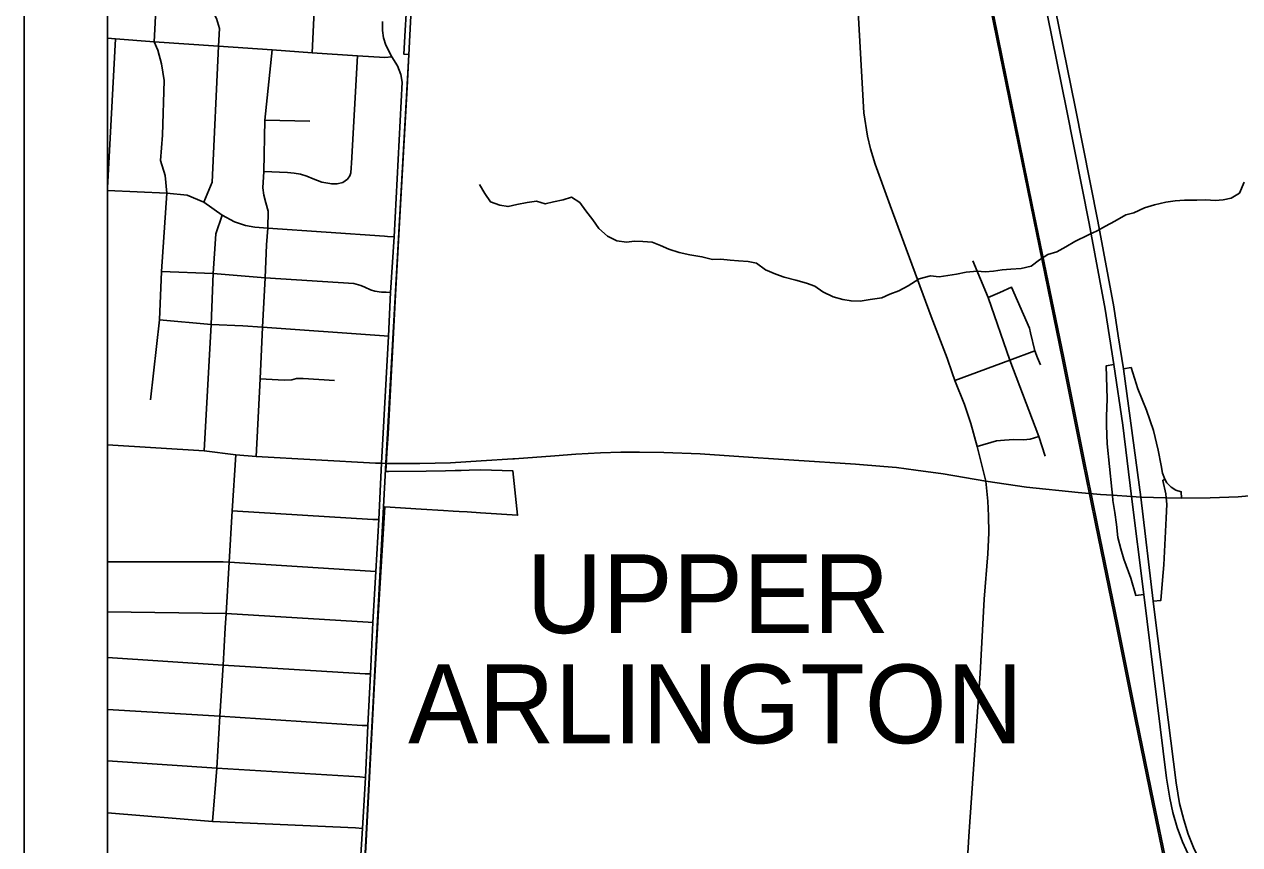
# Model space of a CAD drawing. Extents: x 0 to 34, y 0 to 22.
# Drawn here: x 3.318 to 4.779, y 13.965 to 14.951 of the extents above; entities that cross this region are included whole.
import ezdxf

# ---------------------------------------------------------------- set-up
doc = ezdxf.new("R2010")
doc.units = 0
for name, color, linetype in [('GM_X_City_Street', 7, 'Continuous'), ('GM_X_Corporation', 7, 'Continuous'), ('GM_X_Corporation_Text', 7, 'Continuous'), ('GM_X_County_Road', 7, 'Continuous'), ('GM_X_Interchange_Ramps', 7, 'Continuous'), ('GM_X_Minor_River', 7, 'Continuous'), ('GM_X_Rail_Line', 7, 'Continuous'), ('GM_X_State_Route', 7, 'Continuous'), ('GM_X_Township_Road', 7, 'Continuous'), ('SH_Data', 7, 'Continuous')]:
    doc.layers.add(name, color=color, linetype=linetype)

msp = doc.modelspace()

# ---------------------------------------------------------------- linework, layer by layer
at = {"layer": 'GM_X_City_Street'}
for p, q in [((3.6641, 14.9171), (3.6818, 15.2616)), ((3.4182, 14.7547), (3.428, 14.934)), ((3.6073, 14.8361), (3.6614, 14.8348))]:
    msp.add_line(p, q, dxfattribs=at)
for points in [[(3.4697, 14.5), (3.4807, 14.596), (3.4832, 14.6543), (3.4895, 14.7484), (3.4876, 14.7697), (3.482, 14.7879), (3.4845, 14.818), (3.4864, 14.8838), (3.4832, 14.9039), (3.4788, 14.9202), (3.4744, 14.9302), (3.4916, 15.2614), (3.4922, 15.2751), (3.4936, 15.2887), (3.4949, 15.3045), (3.5, 15.319), (3.5042, 15.3333), (3.5076, 15.3435), (3.5087, 15.3606), (3.5204, 15.5468), (3.5251, 15.614)], [(3.534, 14.7377), (3.544, 14.7615), (3.5516, 14.9252), (3.5528, 14.9465), (3.5491, 14.9584), (3.5422, 14.9722), (3.5365, 14.9891), (3.5503, 15.2711)], [(3.7228, 13.9529), (3.7248, 13.9848), (3.7282, 14.0461), (3.731, 14.1086), (3.7343, 14.1704), (3.737, 14.2323), (3.7409, 14.2935), (3.7442, 14.3562), (3.7475, 14.4237), (3.7562, 14.5767), (3.7585, 14.6291), (3.7628, 14.6959), (3.7723, 14.8819), (3.7707, 14.891), (3.767, 14.9016), (3.76, 14.9125), (3.7529, 14.9262), (3.7499, 14.9353), (3.7487, 14.944), (3.7487, 14.9549)], [(3.4182, 14.9347), (3.428, 14.934), (3.4744, 14.9302), (3.5516, 14.9252), (3.6161, 14.9208), (3.6641, 14.9171), (3.7187, 14.9134), (3.7517, 14.9117), (3.76, 14.9125)], [(3.5968, 14.4318), (3.6017, 14.5252), (3.6046, 14.5874), (3.6076, 14.6467), (3.6095, 14.6863), (3.6102, 14.6964), (3.6109, 14.7065), (3.6112, 14.7266), (3.6087, 14.7368), (3.6061, 14.7462), (3.6048, 14.7549), (3.6063, 14.7746), (3.6073, 14.8361), (3.6161, 14.9208)], [(3.6063, 14.7746), (3.6347, 14.7731), (3.6424, 14.7725), (3.6501, 14.7712), (3.658, 14.7689), (3.6656, 14.7656), (3.6758, 14.7616), (3.6878, 14.7595), (3.6942, 14.7597), (3.7013, 14.7611), (3.7067, 14.7651), (3.7095, 14.7692), (3.7109, 14.773), (3.7111, 14.7787), (3.7115, 14.7845), (3.7187, 14.9134)], [(3.4182, 14.7515), (3.4895, 14.7484), (3.5139, 14.7459), (3.534, 14.7377), (3.556, 14.722), (3.571, 14.7139), (3.5841, 14.7095), (3.5952, 14.7077), (3.6109, 14.7065), (3.7511, 14.6968), (3.755, 14.6965), (3.7628, 14.6959)], [(3.5344, 14.4385), (3.5428, 14.5904), (3.5453, 14.6518), (3.5484, 14.6995), (3.556, 14.722)], [(4.5455, 14.4322), (4.5377, 14.456), (4.5028, 14.5477), (4.477, 14.6228), (4.4585, 14.6672)], [(3.4832, 14.6543), (3.5453, 14.6518), (3.6076, 14.6467), (3.7143, 14.6398), (3.7226, 14.6375), (3.7274, 14.6355), (3.7342, 14.6322), (3.7394, 14.6306), (3.7475, 14.6294), (3.753, 14.6293), (3.7585, 14.6291)], [(3.4807, 14.596), (3.5428, 14.5904), (3.5808, 14.5888), (3.6046, 14.5874), (3.745, 14.5773), (3.7506, 14.577), (3.7562, 14.5767)], [(4.4368, 14.5232), (4.5028, 14.5477), (4.533, 14.559)], [(3.6017, 14.5252), (3.6306, 14.5237), (3.6397, 14.524), (3.6455, 14.5255), (3.6534, 14.5257), (3.6911, 14.5232)], [(4.4636, 14.4437), (4.487, 14.4506), (4.4966, 14.4516), (4.5076, 14.4521), (4.5194, 14.4518), (4.5274, 14.4528), (4.5377, 14.456)], [(3.4182, 14.4458), (3.5344, 14.4385), (3.5726, 14.434), (3.5968, 14.4318), (3.7403, 14.4239), (3.7475, 14.4237)], [(3.9073, 14.4292), (3.956, 14.4326), (3.9812, 14.4346), (4.0108, 14.4363), (4.0355, 14.437), (4.0577, 14.4372), (4.087, 14.4367), (4.1306, 14.4349), (4.1945, 14.4305), (4.2433, 14.4275), (4.3175, 14.4227), (4.3513, 14.4198), (4.3669, 14.4185), (4.3899, 14.4156), (4.4227, 14.4109), (4.4743, 14.4023)], [(3.5443, 13.9931), (3.5495, 14.0573), (3.5532, 14.1195), (3.5571, 14.1811), (3.5596, 14.2258), (3.5609, 14.2429), (3.5643, 14.3047), (3.5681, 14.3665), (3.5726, 14.434)], [(3.7475, 14.4237), (3.753, 14.4236), (3.7578, 14.4235)], [(3.7578, 14.4235), (3.7685, 14.4234), (3.7936, 14.4235), (3.8306, 14.4243), (3.8673, 14.4266), (3.9053, 14.4291), (3.9073, 14.4292)], [(4.4743, 14.4023), (4.5231, 14.395), (4.5853, 14.3884), (4.6119, 14.3863), (4.6263, 14.3855), (4.6493, 14.3837), (4.6603, 14.3828), (4.6907, 14.382), (4.7094, 14.3817), (4.7438, 14.3823), (4.7775, 14.3832), (4.8176, 14.3869)], [(3.5681, 14.3665), (3.7371, 14.3562), (3.7442, 14.3562)], [(3.4182, 14.3053), (3.5573, 14.3052), (3.5643, 14.3047), (3.7342, 14.2939), (3.7409, 14.2935)], [(3.4182, 14.2451), (3.5609, 14.2429), (3.7314, 14.2325), (3.737, 14.2323)], [(3.4182, 14.19), (3.5571, 14.1811), (3.7278, 14.1706), (3.7343, 14.1704)], [(3.4182, 14.1277), (3.5532, 14.1195), (3.7245, 14.1085), (3.731, 14.1086)], [(3.4182, 14.0658), (3.5495, 14.0573), (3.7217, 14.0468), (3.7282, 14.0461)], [(3.4182, 14.0033), (3.5443, 13.9931), (3.7162, 13.9853), (3.7248, 13.9848)]]:
    msp.add_lwpolyline(points, dxfattribs=at)
at = {"layer": 'GM_X_Corporation'}
for points in [[(3.4182, 20.0965), (3.4182, 13.2965), (3.6948, 13.2965), (3.6956, 13.3169), (3.6981, 13.3787), (3.6999, 13.4225), (3.7018, 13.4595), (3.7059, 13.5365), (3.7145, 13.7018), (3.7193, 13.7933), (3.7233, 13.869), (3.7259, 13.9178), (3.7279, 13.9548), (3.7528, 14.4241), (3.7803, 14.9148), (3.798, 15.261), (3.8112, 15.451), (3.8143, 15.5115), (3.8186, 15.5835), (3.8357, 15.8507)], [(3.4182, 17.3523), (3.4182, 13.4384)], [(3.8357, 15.8507), (3.8186, 15.5835), (3.8143, 15.5115), (3.8112, 15.451), (3.798, 15.261), (3.7803, 14.9148), (3.7528, 14.4241), (3.7279, 13.9548), (3.7259, 13.9178), (3.7233, 13.869), (3.7193, 13.7933), (3.7145, 13.7018), (3.7059, 13.5365), (3.7018, 13.4595), (3.6999, 13.4225), (3.6981, 13.3787), (3.6956, 13.3169), (3.6948, 13.2965), (8.5129, 13.2965)], [(3.7285, 13.9545), (3.7388, 14.1529), (3.7439, 14.247), (3.7516, 14.3715), (3.7951, 14.3687), (3.8223, 14.367), (3.8337, 14.3663), (3.8411, 14.3658), (3.8506, 14.3652), (3.8665, 14.3641), (3.9111, 14.3613), (3.9056, 14.4145), (3.8672, 14.4159), (3.8531, 14.4155), (3.8435, 14.4152), (3.8361, 14.4149), (3.8246, 14.4146), (3.8012, 14.4143), (3.756, 14.4139), (3.7528, 14.4139), (3.7542, 14.4364), (3.7555, 14.4592), (3.7645, 14.6264), (3.7707, 14.7416), (3.7784, 14.8756), (3.7803, 14.9152), (3.7746, 14.9154), (3.7762, 14.9441), (3.7772, 14.964)], [(3.7772, 14.964), (3.7762, 14.9441), (3.7746, 14.9154), (3.7803, 14.9152), (3.7784, 14.8756), (3.7707, 14.7416), (3.7645, 14.6264), (3.7555, 14.4592), (3.7542, 14.4364), (3.7528, 14.4139), (3.756, 14.4139), (3.8012, 14.4143), (3.8246, 14.4146), (3.8361, 14.4149), (3.8435, 14.4152), (3.8531, 14.4155), (3.8672, 14.4159), (3.9056, 14.4145), (3.9111, 14.3613), (3.8665, 14.3641), (3.8506, 14.3652), (3.8411, 14.3658), (3.8337, 14.3663), (3.8223, 14.367), (3.7951, 14.3687), (3.7516, 14.3715), (3.7439, 14.247), (3.7388, 14.1529), (3.7285, 13.9545)]]:
    msp.add_lwpolyline(points, dxfattribs=at)
at = {"layer": 'GM_X_County_Road'}
for points in [[(4.4336, 14.5325), (4.4275, 14.5502), (4.4083, 14.6003), (4.3592, 14.7336), (4.3411, 14.7833), (4.3353, 14.8017), (4.3317, 14.8169), (4.3276, 14.8452), (4.3196, 14.9884), (4.3108, 15.1016), (4.308, 15.1233), (4.303, 15.144), (4.2974, 15.1597), (4.2877, 15.1814), (4.2711, 15.21), (4.2553, 15.2307)], [(4.4548, 13.9928), (4.4671, 14.1709), (4.4722, 14.2604), (4.4767, 14.3148), (4.4779, 14.3401), (4.4774, 14.3607), (4.4764, 14.3782), (4.4743, 14.4023), (4.4636, 14.4437), (4.4559, 14.4715), (4.4483, 14.4944), (4.4368, 14.5232), (4.4336, 14.5325)], [(4.4428, 13.7933), (4.4536, 13.9748), (4.4548, 13.9928)]]:
    msp.add_lwpolyline(points, dxfattribs=at)
at = {"layer": 'GM_X_Interchange_Ramps'}
for points in [[(4.6279, 14.5424), (4.6186, 14.5408), (4.6198, 14.501), (4.6193, 14.4798)], [(4.7094, 14.3817), (4.7091, 14.3894), (4.7024, 14.3912), (4.6968, 14.3948), (4.6918, 14.4002), (4.6891, 14.4045), (4.6864, 14.4118), (4.685, 14.4212), (4.6814, 14.4394), (4.6755, 14.4629), (4.6672, 14.4877), (4.6569, 14.5131), (4.6487, 14.5387), (4.6394, 14.5373)], [(4.6193, 14.4798), (4.619, 14.4692), (4.6201, 14.4472), (4.6257, 14.3926), (4.6263, 14.3855)], [(4.6907, 14.382), (4.6905, 14.3869), (4.6868, 14.4031), (4.6891, 14.4045)], [(4.6263, 14.3855), (4.6268, 14.3788), (4.6293, 14.3646), (4.631, 14.35), (4.6328, 14.3344), (4.6364, 14.3208), (4.6399, 14.3083)], [(4.6864, 14.283), (4.6879, 14.3017), (4.6909, 14.3578), (4.6918, 14.3745), (4.6907, 14.382)], [(4.6399, 14.3083), (4.6484, 14.2855), (4.6544, 14.2648), (4.6641, 14.2659)], [(4.6754, 14.2579), (4.6845, 14.2588), (4.6864, 14.283)]]:
    msp.add_lwpolyline(points, dxfattribs=at)
at = {"layer": 'GM_X_Minor_River'}
msp.add_lwpolyline([(3.8656, 14.7588), (3.8719, 14.7481), (3.8786, 14.7381), (3.8899, 14.7341), (3.8997, 14.7324), (3.9104, 14.735), (3.9229, 14.7374), (3.9339, 14.7388), (3.9445, 14.7356), (3.9544, 14.7381), (3.9658, 14.7406), (3.9761, 14.7435), (3.9862, 14.7372), (3.9933, 14.7273), (4.0015, 14.7165), (4.0089, 14.7058), (4.0194, 14.6969), (4.0307, 14.691), (4.0421, 14.6897), (4.0519, 14.6907), (4.0618, 14.6902), (4.0731, 14.6896), (4.0829, 14.6857), (4.0931, 14.6813), (4.1056, 14.677), (4.1184, 14.6741), (4.1328, 14.672), (4.1456, 14.6688), (4.1555, 14.669), (4.1668, 14.6677), (4.1767, 14.6672), (4.1884, 14.6662), (4.1983, 14.6642), (4.2091, 14.6564), (4.2216, 14.6509), (4.2318, 14.6474), (4.2457, 14.6437), (4.2586, 14.6401), (4.2684, 14.6366), (4.2781, 14.63), (4.2906, 14.6237), (4.3023, 14.6205), (4.3121, 14.6188), (4.3231, 14.6187), (4.3349, 14.6204), (4.3489, 14.6225), (4.3588, 14.6269), (4.3695, 14.6309), (4.3806, 14.6372), (4.394, 14.6453), (4.4077, 14.6489), (4.4179, 14.648), (4.4388, 14.6511), (4.4506, 14.6536), (4.4635, 14.6546), (4.4733, 14.6537), (4.4835, 14.6547), (4.4938, 14.6564), (4.504, 14.657), (4.5166, 14.658), (4.5287, 14.6608), (4.5387, 14.6683), (4.5486, 14.6746), (4.5593, 14.6778), (4.5704, 14.6838), (4.5811, 14.6904), (4.5975, 14.6982), (4.6081, 14.7033), (4.6181, 14.7089), (4.6291, 14.7148), (4.6425, 14.7222), (4.652, 14.7247), (4.665, 14.7306), (4.6768, 14.7346), (4.6905, 14.7378), (4.7019, 14.7392), (4.7129, 14.7402), (4.7277, 14.7399), (4.7387, 14.7405), (4.7496, 14.7396), (4.7595, 14.7406), (4.769, 14.7424), (4.7789, 14.7483), (4.7848, 14.7615)], dxfattribs=at)
at = {"layer": 'GM_X_Rail_Line'}
for points in [[(4.7805, 13.4938), (4.7512, 13.6369), (4.7349, 13.717), (4.7207, 13.7855), (4.7132, 13.8245), (4.6897, 13.9404), (4.6741, 14.0158), (4.6537, 14.1156), (4.6312, 14.2278), (4.6059, 14.351), (4.5939, 14.4103), (4.592, 14.4199), (4.566, 14.55), (4.528, 14.7339), (4.4614, 15.0618), (4.4418, 15.1608), (4.4065, 15.3283), (4.37, 15.5031), (4.3467, 15.6199), (4.3024, 15.8387)], [(4.7824, 13.4941), (4.7531, 13.6373), (4.7368, 13.7174), (4.7226, 13.7859), (4.7151, 13.8248), (4.6916, 13.9408), (4.6759, 14.0162), (4.6556, 14.1159), (4.6331, 14.2281), (4.6078, 14.3514), (4.5958, 14.4107), (4.5939, 14.4202), (4.5679, 14.5503), (4.5299, 14.7343), (4.4633, 15.0621), (4.4437, 15.1611), (4.4084, 15.3287), (4.3719, 15.5034), (4.3486, 15.6203), (4.3043, 15.8391)]]:
    msp.add_lwpolyline(points, dxfattribs=at)
at = {"layer": 'GM_X_State_Route'}
for points in [[(4.7192, 13.9493), (4.7105, 13.9685), (4.7041, 13.986), (4.6991, 14.004), (4.6951, 14.0212), (4.6914, 14.0453), (4.6641, 14.2659), (4.6493, 14.3837), (4.6386, 14.4695), (4.6279, 14.5424), (4.6176, 14.6089), (4.5985, 14.712), (4.5709, 14.8495), (4.5422, 14.9919), (4.5179, 15.0936), (4.4822, 15.2226), (4.4373, 15.3736), (4.4206, 15.4314), (4.4117, 15.4643), (4.3965, 15.5256), (4.383, 15.5846), (4.377, 15.617), (4.3667, 15.6696)], [(4.6333, 14.577), (4.628, 14.6117), (4.6089, 14.7148), (4.5813, 14.8523), (4.5526, 14.9946), (4.5344, 15.0751), (4.5317, 15.0847)], [(4.6778, 14.2384), (4.6754, 14.2579), (4.6603, 14.3828), (4.6394, 14.5373), (4.6333, 14.577)], [(4.7713, 13.8945), (4.7677, 13.8982), (4.7544, 13.9118), (4.7432, 13.9269), (4.7324, 13.9438), (4.7239, 13.9616), (4.7173, 13.9778), (4.712, 13.9951), (4.707, 14.0147), (4.7028, 14.0394), (4.6778, 14.2384)]]:
    msp.add_lwpolyline(points, dxfattribs=at)
at = {"layer": 'GM_X_Township_Road'}
for points in [[(4.5278, 14.5806), (4.5265, 14.586), (4.5049, 14.6355), (4.491, 14.6291), (4.477, 14.6228)], [(4.5397, 14.5419), (4.5363, 14.5505), (4.533, 14.559), (4.5278, 14.5806)]]:
    msp.add_lwpolyline(points, dxfattribs=at)
at = {"layer": 'SH_Data'}
for p, q in [((3.3182, 20.1965), (3.3182, 13.1965)), ((3.4182, 20.0965), (3.4182, 13.2965))]:
    msp.add_line(p, q, dxfattribs=at)

# ---------------------------------------------------------------- texts
at = {"layer": 'GM_X_Corporation_Text'}
for s, p in [('UPPER', (3.9218, 14.2195)), ('ARLINGTON', (3.7797, 14.0871))]:
    msp.add_text(s, height=0.0947, rotation=0, dxfattribs=at).set_placement(p)

doc.saveas('drawing.dxf')
